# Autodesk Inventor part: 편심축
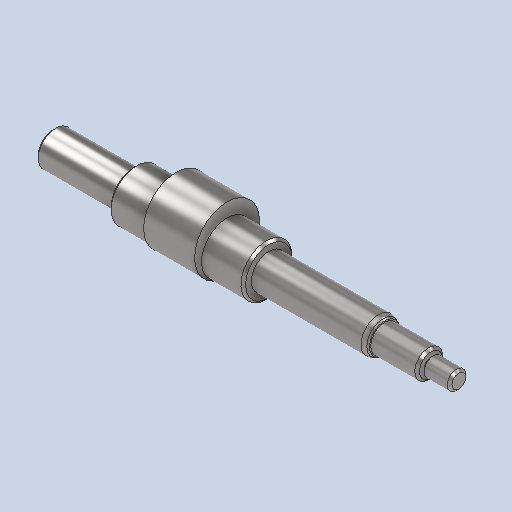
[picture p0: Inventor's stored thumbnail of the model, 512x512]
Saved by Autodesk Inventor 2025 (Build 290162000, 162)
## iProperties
Created: 2024-07
Part Number: 편심축
Material: 강철, 연강
Document SubType Name: Modeling
Designer: myung
Density: 7.86 g/cm^3
Appearance: 기본값
Author: jhkim
Sending System: Autodesk Inventor 2025
Preprocessor: ST-DEVELOPER v20
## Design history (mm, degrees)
feature "솔리드1"
node "솔리드2"
